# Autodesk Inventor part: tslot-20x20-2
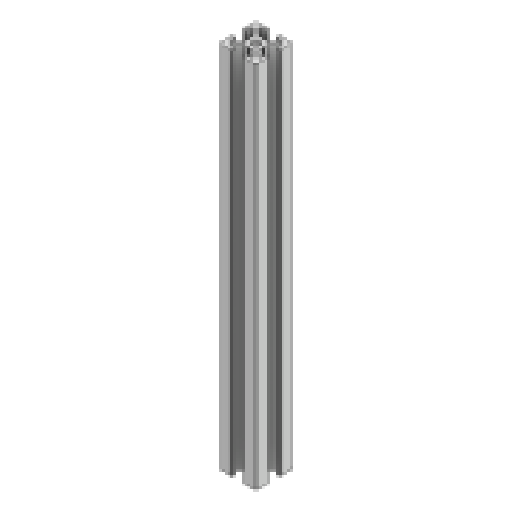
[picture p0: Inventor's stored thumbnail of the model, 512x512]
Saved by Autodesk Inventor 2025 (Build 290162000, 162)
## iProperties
Created: 2025-03
Part Number: tslot-20x20-2
Material: Generico
Document SubType Name: Modeling
Designer: Ryzen5700u
Density: 1 g/cm^3
Appearance: Default
Author: Ryzen5700u
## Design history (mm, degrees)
feature "Base1"
sketch "Schizzo1"
  geometry: L1 (3.761, -16)-(4.7, -16) reference; L2 (3.761, -16)-(0.7, -12.939) reference; L3 (0.7, -12.939)-(0.7, -10.52) reference; L4 (0.4, -10)-(0.7, -10.52) reference; L5 (0.4, -10)-(0.7, -9.48) reference; L6 (0.7, -7.061)-(0.7, -9.48) reference; L7 (3.761, -4)-(0.7, -7.061) reference; L8 (3.761, -4)-(4.7, -4) reference; L9 (4.7, -4)-(4.7, -7) reference; L10 (4.7, -7)-(6.4, -7) reference; L11 (6.7, -6.7)-(6.7, -1) reference; L12 (5.7, 0)-(0, 0) reference; L13 (-0.3, -2)-(-0.3, -0.3) reference; L14 (2.7, -2)-(-0.3, -2) reference; L15 (2.7, -2.939)-(2.7, -2) reference; L16 (2.7, -2.939)-(-0.361, -6) reference; L17 (-0.361, -6)-(-2.78, -6) reference; L18 (-3.3, -6.3)-(-2.78, -6) reference; L19 (-3.3, -6.3)-(-3.82, -6) reference; L20 (-6.239, -6)-(-3.82, -6) reference; L21 (-9.3, -2.939)-(-6.239, -6) reference; L22 (-9.3, -2.939)-(-9.3, -2) reference; L23 (-9.3, -2)-(-6.3, -2) reference; L24 (-6.3, -2)-(-6.3, -0.3) reference; L25 (-12.3, 0)-(-6.6, 0) reference; L26 (-13.3, -6.7)-(-13.3, -1) reference; L27 (-11.3, -7)-(-13, -7) reference; L28 (-11.3, -4)-(-11.3, -7) reference; L29 (-10.361, -4)-(-11.3, -4) reference; L30 (-10.361, -4)-(-7.3, -7.061) reference; L31 (-7.3, -7.061)-(-7.3, -9.48) reference; L32 (-7, -10)-(-7.3, -9.48) reference; L33 (-7, -10)-(-7.3, -10.52) reference; L34 (-7.3, -12.939)-(-7.3, -10.52) reference; L35 (-10.361, -16)-(-7.3, -12.939) reference; L36 (-10.361, -16)-(-11.3, -16) reference; L37 (-11.3, -16)-(-11.3, -13) reference; L38 (-11.3, -13)-(-13, -13) reference; L39 (-13.3, -13.3)-(-13.3, -19) reference; L40 (-12.3, -20)-(-6.6, -20) reference; L41 (-6.3, -18)-(-6.3, -19.7) reference; L42 (-9.3, -18)-(-6.3, -18) reference; L43 (-9.3, -17.061)-(-9.3, -18) reference; L44 (-9.3, -17.061)-(-6.239, -14) reference; L45 (-6.239, -14)-(-3.82, -14) reference; L46 (-3.3, -13.7)-(-3.82, -14) reference; L47 (-3.3, -13.7)-(-2.78, -14) reference; L48 (-0.361, -14)-(-2.78, -14) reference; L49 (2.7, -17.061)-(-0.361, -14) reference; L50 (2.7, -17.061)-(2.7, -18) reference; L51 (2.7, -18)-(-0.3, -18) reference; L52 (-0.3, -18)-(-0.3, -19.7) reference; L53 (5.7, -20)-(0, -20) reference; L54 (6.7, -13.3)-(6.7, -19) reference; L55 (4.7, -13)-(6.4, -13) reference; L56 (4.7, -16)-(4.7, -13) reference; C1 r 2.1 at (-3.3, -10) reference; A1 r 0.3 centre (6.4, -6.7) between (6.4, -7) and (6.7, -6.7) reference; A2 r 1 centre (5.7, -1) between (6.7, -1) and (5.7, 0) reference; A3 r 0.3 centre (0, -0.3) between (0, 0) and (-0.3, -0.3) reference; A4 r 0.3 centre (-6.6, -0.3) between (-6.3, -0.3) and (-6.6, 0) reference; A5 r 1 centre (-12.3, -1) between (-12.3, 0) and (-13.3, -1) reference; A6 r 0.3 centre (-13, -6.7) between (-13.3, -6.7) and (-13, -7) reference; A7 r 0.3 centre (-13, -13.3) between (-13, -13) and (-13.3, -13.3) reference; A8 r 1 centre (-12.3, -19) between (-13.3, -19) and (-12.3, -20) reference; A9 r 0.3 centre (-6.6, -19.7) between (-6.6, -20) and (-6.3, -19.7) reference; A10 r 0.3 centre (0, -19.7) between (-0.3, -19.7) and (0, -20) reference; A11 r 1 centre (5.7, -19) between (5.7, -20) and (6.7, -19) reference; A12 r 0.3 centre (6.4, -13.3) between (6.7, -13.3) and (6.4, -13) reference; 1 further point
extrude "Estrusione1" join sketch "Schizzo1" distance "d0" = 190; taper "d1" = 0 deg
node "Solido1"
node "Linea chiusa proiettata1"
